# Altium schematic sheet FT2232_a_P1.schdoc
size 594 x 419 mm; Symbol: Drawing-Symbol_A4; @Project Name: FPGA_motors_V3_0; @Page Count: 1; @Update Date: 2025-11-25; @Create Date: 2025-11-25; @Schematic Name: FT2232_a; @Page No: 1; @Page Name: P1; Company: EasyEDA.com; Version: V1.0; Page Size: A4; @Create Time: 20:24:01; @Update Time: 21:28:17; Border: 1; Width: 2338; Height: 1652; Region Start: 1; X Region Count: 6; Y Region Count: 4; Blade Width: 10; Title Block Position: 3; Device: Drawing-Symbol_A4
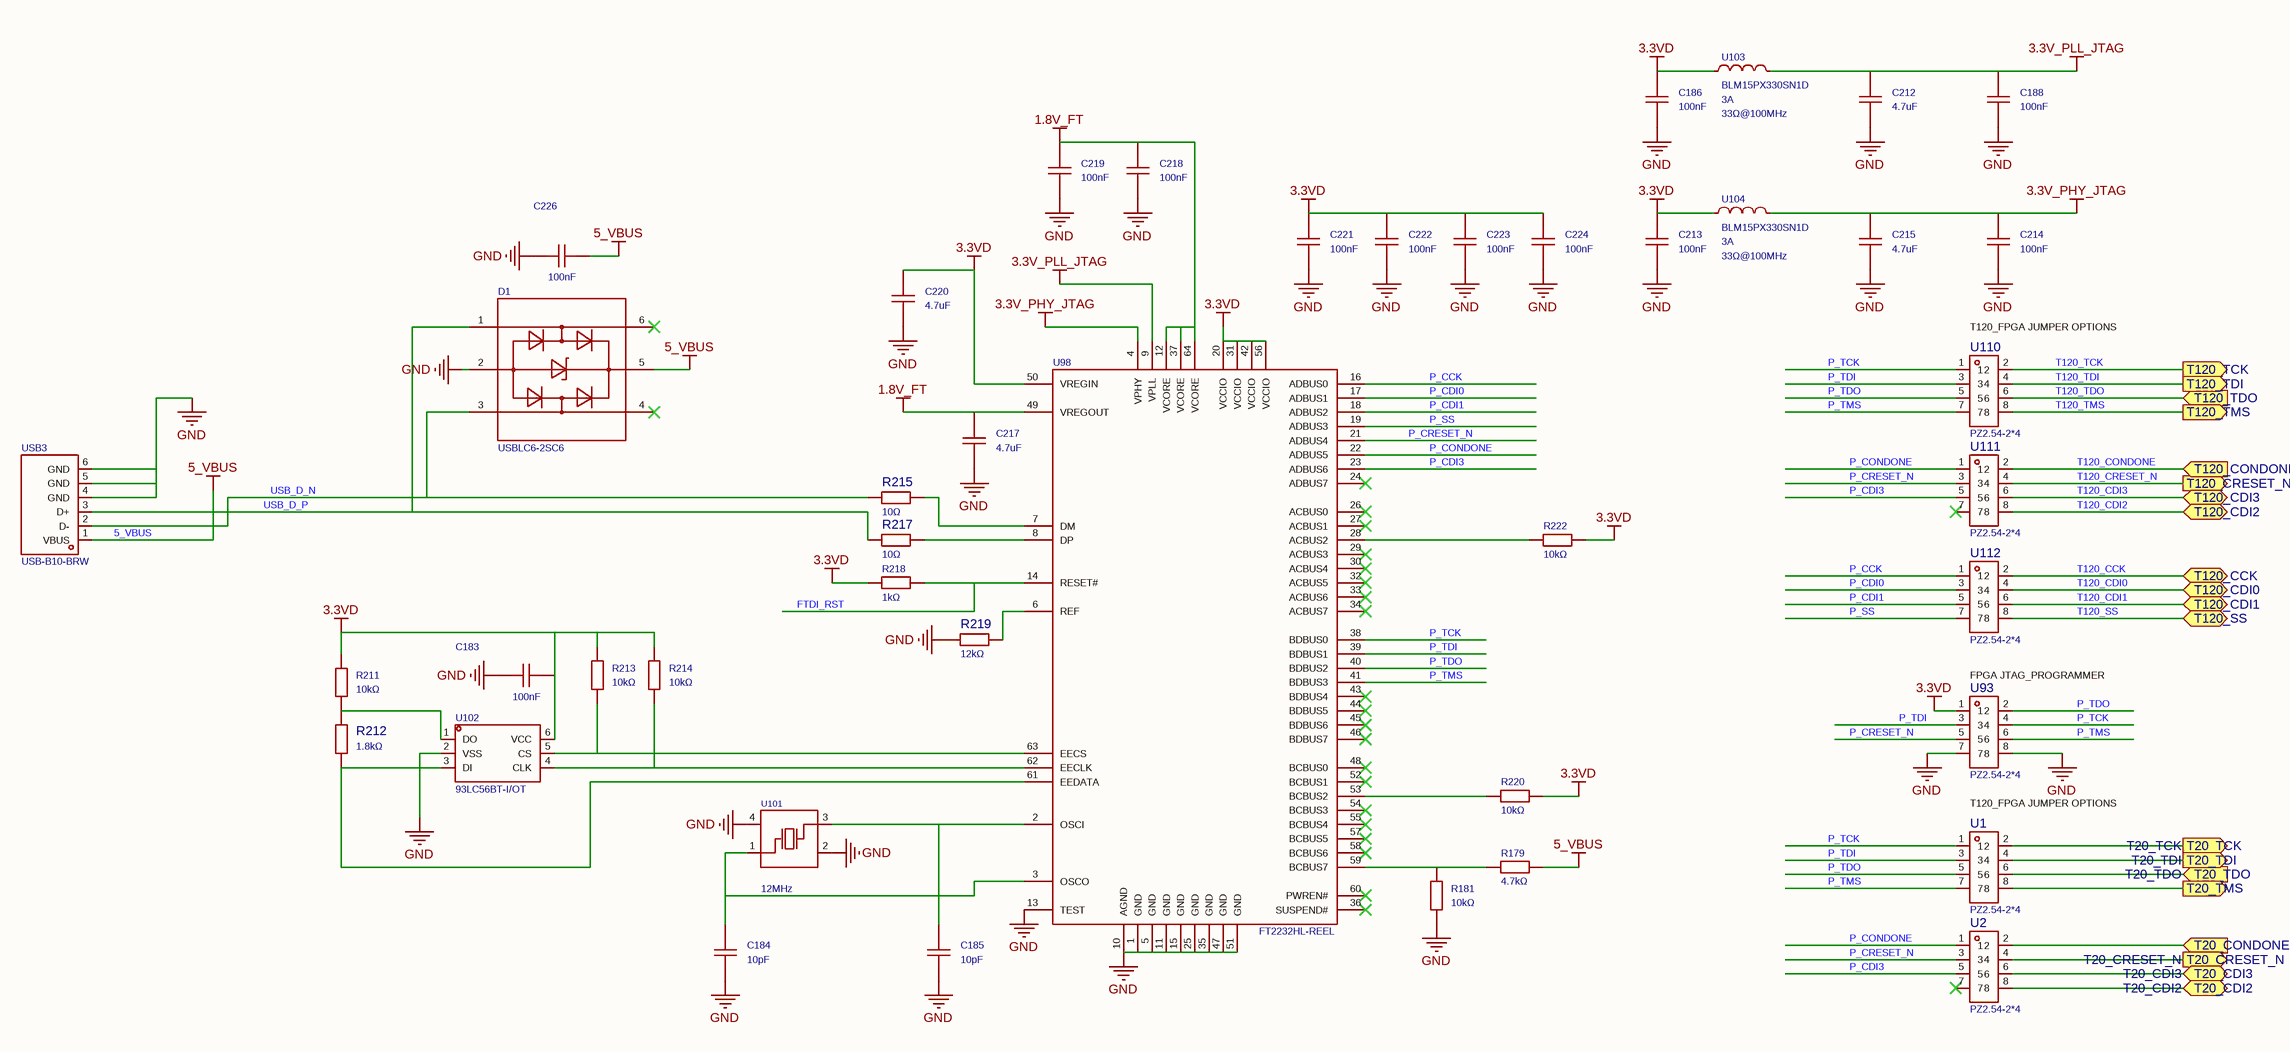
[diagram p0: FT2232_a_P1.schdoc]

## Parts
C183  100nF  [C0402]
C184  10pF  [C0402]
C185  10pF  [C0402]
C186  100nF  [C0201]
C188  100nF  [C0201]
C212  value 4.7uF  [C0402]  (hidden comment: CL05A475MP5NRNC)
C213  100nF  [C0201]
C214  100nF  [C0201]
C215  value 4.7uF  [C0402]  (hidden comment: CL05A475MP5NRNC)
C217  value 4.7uF  [C0402]  (hidden comment: CL05A475MP5NRNC)
C218  100nF  [C0201]
C219  100nF  [C0201]
C220  value 4.7uF  [C0402]  (hidden comment: CL05A475MP5NRNC)
C221  100nF  [C0201]
C222  100nF  [C0201]
C223  100nF  [C0201]
C224  100nF  [C0201]
C226  100nF  [C0402]
D1  USBLC6-2SC6  [SOT-23-6_L2.9-W1.6-P0.95-LS2.8-BL]
R179  4.7kΩ  [R0402]
R181  10kΩ  [R0402]
R211  10kΩ  [R0402]
R212  1.8kΩ  [R0402]
R213  10kΩ  [R0402]
R214  10kΩ  [R0402]
R215  10Ω  [R0402]
R217  10Ω  [R0402]
R218  1kΩ  [R0402]
R219  12kΩ  [R0402]
R220  10kΩ  [R0402]
R222  10kΩ  [R0402]
U1  PZ2.54-2*4  [HDR-TH_8P-P2.54-V-M-R2-C4-S2.54]
U2  PZ2.54-2*4  [HDR-TH_8P-P2.54-V-M-R2-C4-S2.54]
U93  PZ2.54-2*4  [HDR-TH_8P-P2.54-V-M-R2-C4-S2.54]
U98  FT2232HL-REEL  [LQFP-64_L10.0-W10.0-P0.50-LS12.0-TL]
U101  12MHz  [CRYSTAL-SMD_4P-L3.2-W2.5-BL]
U102  93LC56BT-I/OT  [SOT-23-6_L2.9-W1.6-P0.95-LS2.8-BR]
U103  BLM15PX330SN1D  Impedance @ Frequency: 33Ω@100MHz  Current Rating: 3A  [L0402]
U104  BLM15PX330SN1D  Impedance @ Frequency: 33Ω@100MHz  Current Rating: 3A  [L0402]
U110  PZ2.54-2*4  [HDR-TH_8P-P2.54-V-M-R2-C4-S2.54]
U111  PZ2.54-2*4  [HDR-TH_8P-P2.54-V-M-R2-C4-S2.54]
U112  PZ2.54-2*4  [HDR-TH_8P-P2.54-V-M-R2-C4-S2.54]
USB3  USB-B10-BRW  [USB-B-TH_USB-B10-BRW]

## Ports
T20_CDI2 (bidir), T20_CDI3 (bidir), T20_CONDONE (in), T20_CRESET_N (out), T20_TCK (out), T20_TDI (out), T20_TDO (in), T20_TMS (out), T120_CCK (bidir), T120_CDI0 (bidir), T120_CDI1 (bidir), T120_CDI2 (bidir), T120_CDI3 (bidir), T120_CONDONE (in), T120_CRESET_N (out), T120_SS (bidir), T120_TCK (out), T120_TDI (out), T120_TDO (in), T120_TMS (out)

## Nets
1.8V_FT: C217.2 C218.1 C219.1 U98.12(VCORE) U98.37(VCORE) U98.49(VREGOUT) U98.64(VCORE)
3.3V_PHY_JTAG: C214.1 C215.2 U98.4(VPHY) U104.2
3.3V_PLL_JTAG: C188.1 C212.2 U98.9(VPLL) U103.2
3.3VD: C183.2 C186.1 C213.1 C220.2 C221.1 C222.1 C223.1 C224.1 R211.2 R213.2 R214.2 R218.1 R220.1 R222.1 U93.1 U98.20(VCCIO) U98.31(VCCIO) U98.42(VCCIO) U98.50(VREGIN) U98.56(VCCIO) U102.6(VCC) U103.1 U104.1
5_VBUS: C226.2 D1.5 R179.2 USB3.1(VBUS)
GND: C183.1 C184.1 C185.1 C186.2 C188.2 C212.1 C213.2 C214.2 C215.1 C217.1 C218.2 C219.2 C220.1 C221.2 C222.2 C223.2 C224.2 C226.1 D1.2 R181.1 R219.1 U93.7 U93.8 U98.1(GND) U98.5(GND) U98.10(AGND) U98.11(GND) U98.13(TEST) U98.15(GND) U98.25(GND) U98.35(GND) U98.47(GND) U98.51(GND) U101.2(Gnd) U101.4(Gnd) U102.2(VSS) USB3.4(GND) USB3.5(GND) USB3.6(GND)
FTDI_RST: R218.2 U98.14(RESET#)
P_CCK: U98.16(ADBUS0) U112.1
P_CDI0: U98.17(ADBUS1) U112.3
P_CDI1: U98.18(ADBUS2) U112.5
P_CDI3: U2.5 U98.23(ADBUS6) U111.5
P_CONDONE: U2.1 U98.22(ADBUS5) U111.1
P_CRESET_N: U2.3 U93.5 U98.21(ADBUS4) U111.3
P_SS: U98.19(ADBUS3) U112.7
P_TCK: U1.1 U93.4 U98.38(BDBUS0) U110.1
P_TDI: U1.3 U93.3 U98.39(BDBUS1) U110.3
P_TDO: U1.5 U93.2 U98.40(BDBUS2) U110.5
P_TMS: U1.7 U93.6 U98.41(BDBUS3) U110.7
T20_CDI2: U2.8 ; port T20_CDI2
T20_CDI3: U2.6 ; port T20_CDI3
T20_CONDONE: U2.2 ; port T20_CONDONE
T20_CRESET_N: U2.4 ; port T20_CRESET_N
T20_TCK: U1.2 ; port T20_TCK
T20_TDI: U1.4 ; port T20_TDI
T20_TDO: U1.6 ; port T20_TDO
T20_TMS: U1.8 ; port T20_TMS
T120_CCK: U112.2 ; port T120_CCK
T120_CDI0: U112.4 ; port T120_CDI0
T120_CDI1: U112.6 ; port T120_CDI1
T120_CDI2: U111.8 ; port T120_CDI2
T120_CDI3: U111.6 ; port T120_CDI3
T120_CONDONE: U111.2 ; port T120_CONDONE
T120_CRESET_N: U111.4 ; port T120_CRESET_N
T120_SS: U112.8 ; port T120_SS
T120_TCK: U110.2 ; port T120_TCK
T120_TDI: U110.4 ; port T120_TDI
T120_TDO: U110.6 ; port T120_TDO
T120_TMS: U110.8 ; port T120_TMS
USB_D_N: D1.3 R215.1 USB3.2(D-)
USB_D_P: D1.1 R217.1 USB3.3(D+)
NetC184_2: C184.2 U98.3(OSCO) U101.1(In/Out)
NetC185_2: C185.2 U98.2(OSCI) U101.3(Out/In)
NetR179_1: R179.1 R181.2 U98.59(BCBUS7)
NetR211_1: R211.1 R212.2 U102.1(DO)
NetR212_1: R212.1 U98.61(EEDATA) U102.3(DI)
NetR213_1: R213.1 U98.63(EECS) U102.5(CS)
NetR214_1: R214.1 U98.62(EECLK) U102.4(CLK)
NetR215_2: R215.2 U98.7(DM)
NetR217_2: R217.2 U98.8(DP)
NetR219_2: R219.2 U98.6(REF)
NetR220_2: R220.2 U98.53(BCBUS2)
NetR222_2: R222.2 U98.28(ACBUS2)

Not connected (* = marked no-connect by the designer): D1 4* 6*; U2 7*; U98 24(ADBUS7)* 26(ACBUS0)* 27(ACBUS1)* 29(ACBUS3)* 30(ACBUS4)* 32(ACBUS5)* 33(ACBUS6)* 34(ACBUS7)* 36(SUSPEND#)* 43(BDBUS4)* 44(BDBUS5)* 45(BDBUS6)* 46(BDBUS7)* 48(BCBUS0)* 52(BCBUS1)* 54(BCBUS3)* 55(BCBUS4)* 57(BCBUS5)* 58(BCBUS6)* 60(PWREN#)*; U111 7*

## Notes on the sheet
- (near U110) T120_FPGA JUMPER OPTIONS
- (near U93) FPGA JTAG_PROGRAMMER
- T120_FPGA JUMPER OPTIONS

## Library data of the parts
C183 = CL05B104KB54PNC: Capacitance: Tolerance:±10% Tolerance:±10% Voltage Rated: Temperature Coefficient:; Manufacturer: SAMSUNG(三星); Add into BOM: no; Check: true; ConvertToPcb: yes; ModelId: b7d13df3e9464d7a99d0651d1a5b4d57; ModelName: C0402_L1.0-W0.5-H0.5; ModelTransform: 39.37,19.685,0,0,0,0,0,0,0; Tolerance: ±10%
C184 C185 = CL05C100JB5NNNC: Capacitance:10pF Tolerance:±5% Tolerance:±5% Voltage Rating:50V Temperature Coefficient:C0G; Manufacturer: SAMSUNG(三星); AddInBom: yes; ModelId: b7d13df3e9464d7a99d0651d1a5b4d57; ModelName: C0402_L1.0-W0.5-H0.5; ModelTransform: 39.37,19.685,0,0,0,0,0,0,0; Tolerance: ±5%; Voltage Rating: 50V; Temperature Coefficient: C0G
C186 C188 C213 C214 C218 C219 C221-C224 = CL03A104KP3NNNC: Capacitance:100nF Tolerance:±10% Tolerance:±10% Voltage Rating:10V Temperature Coefficient:X5R; Manufacturer: SAMSUNG(三星); Add into BOM: yes; 3D Model: c3e75c3d90204c70b153866ab54c789f; 3D Model Transform: 23.622,11.811,0,0,0,0,0,0,0; Tolerance: ±10%; Temperature Coefficient: X5R; Voltage Rating: 10V; ModelName: C0201_L0.6-W0.3-H0.3
C212 C215 C217 C220 = CL05A475MP5NRNC: Capacitance:4.7uF Tolerance:±20% Tolerance:±20% Voltage Rating:10V Temperature Coefficient:X5R; Manufacturer: SAMSUNG(三星); Temperature Coefficient: X5R; Voltage Rating: 10V; AddInBom: yes; ModelId: b7d13df3e9464d7a99d0651d1a5b4d57; ModelName: C0402_L1.0-W0.5-H0.5; ModelTransform: 39.37,19.685,0,0,0,0,0,0,0; Tolerance: ±20%
C226 = CL05B104KB54PNC: Capacitance: Tolerance:±10% Tolerance:±10% Voltage Rated: Temperature Coefficient:; Manufacturer: SAMSUNG(三星); Add into BOM: yes; Check: true; ModelId: b7d13df3e9464d7a99d0651d1a5b4d57; ModelName: C0402_L1.0-W0.5-H0.5; ModelTransform: 39.37,19.685,0,0,0,0,0,0,0; Tolerance: ±10%
D1 = USBLC6-2SC6_C7519: Polarity:Unidirectional Reverse Stand-Off Voltage (Vrwm):5.25V Clamping Voltage:17V Peak Pulse Current (Ipp):5A Voltage - Breakdown:6V Reverse Leakage Current (Ir):150nA Number of Channels:2 Operating Temperature:-40℃~+125℃ Operating Temperature:-40℃~+125; Manufacturer: ST(意法半导体); AddInBom: yes; ModelId: 1370be37a17e44418ae52e2b4cc1f5e5; ModelName: SOT-23-6_L2.9-W1.6-H1.5-LS2.8-P0.95; ModelTransform: 110.236,113.364,0,90,0,0,0.0005,0.0005,0; Reverse Stand-Off Voltage (Vrwm): 5.25V; Clamping Voltage: 17V; Peak Pulse Current (Ipp): 5A; Voltage - Breakdown: 6V; Reverse Leakage Current (Ir): 150nA; Number of Channels: 2; level of protection: IEC 61000-4-2; Type: ESD; Junction Capacitance: 3.5pF
R179 = 0402WGF4701TCE: Type:Thick Film Resistors Resistance:4.7kΩ Tolerance:±1% Tolerance:±1% Power(Watts): Overload Voltage (Max): Temperature Coefficient:±100ppm/℃ Temperature Coefficient:±100ppm/℃ Operating Temperature Range:-55℃~+155℃ Operating Temperature Range:-55℃~+155℃; Manufacturer: UNI-ROYAL(厚声); Symbol: RT0402BRD074K7L; AddInBom: yes; ModelId: efdecb7dae4442949d28eecaf748420f0819f05c4eef4c71ace90d822a990e87; ModelName: R0402_L1.0-W0.5-H0.4; ModelTransform: 39.37,19.685,0,0,0,0,0,0,0; Tolerance: ±1%; Power(Watts): 62.5mW; Voltage-Supply(Max): 50V
R181 R211 R213 R214 R220 R222 = 0402WGF1002TCE: Type:Thick Film Resistors Resistance:10kΩ Tolerance:±1% Tolerance:±1% Power(Watts): Overload Voltage (Max): Temperature Coefficient:±100ppm/℃ Temperature Coefficient:±100ppm/℃ Operating Temperature Range:-55℃~+155℃ Operating Temperature Range:-55℃~+155℃; Manufacturer: UNI-ROYAL(厚声); AddInBom: yes; ModelId: efdecb7dae4442949d28eecaf748420f; ModelName: R0402_L1.0-W0.5-H0.4; ModelTransform: 39.37,19.685,0,0,0,0,0,0,0; Tolerance: ±1%
R212 = 0402WGF1801TCE: Type:Thick Film Resistor Resistance:1.8kΩ Tolerance:±1% Tolerance:±1% Power(Watts):62.5mW Voltage-Supply(Max):50V Temperature Coefficient:±100ppm/℃ Temperature Coefficient:±100ppm/℃ Operating Temperature:-55℃~+155℃ Operating Temperature:-55℃~+155℃; Manufacturer: UNI-ROYAL(厚声); AddInBom: yes; ModelId: efdecb7dae4442949d28eecaf748420f0819f05c4eef4c71ace90d822a990e87; ModelName: R0402_L1.0-W0.5-H0.4; ModelTransform: 39.37,19.685,0,0,0,0,0,0,0; Tolerance: ±1%; Power(Watts): 62.5mW; Voltage-Supply(Max): 50V
R215 R217 = 0402WGF100JTCE: Type:Thick Film Resistor Resistance:10Ω Tolerance:±1% Tolerance:±1% Power(Watts):62.5mW Voltage-Supply(Max):50V Temperature Coefficient:±200ppm/℃ Temperature Coefficient:±200ppm/℃ Operating Temperature:-55℃~+155℃ Operating Temperature:-55℃~+155℃; Manufacturer: UNI-ROYAL(厚声); AddInBom: yes; ModelId: efdecb7dae4442949d28eecaf748420f; ModelName: R0402_L1.0-W0.5-H0.4; ModelTransform: 39.37,19.685,0,0,0,0,0,0,0; Tolerance: ±1%; Power(Watts): 62.5mW; Voltage-Supply(Max): 50V
R218 = 0402WGF1001TCE: Type:Thick Film Resistor Resistance:1kΩ Tolerance:±1% Tolerance:±1% Power(Watts):62.5mW Voltage-Supply(Max):50V Temperature Coefficient:±100ppm/℃ Temperature Coefficient:±100ppm/℃ Operating Temperature:-55℃~+155℃ Operating Temperature:-55℃~+155℃; Manufacturer: UNI-ROYAL(厚声); AddInBom: yes; ModelId: efdecb7dae4442949d28eecaf748420f0819f05c4eef4c71ace90d822a990e87; ModelName: R0402_L1.0-W0.5-H0.4; ModelTransform: 39.37,19.685,0,0,0,0,0,0,0; Tolerance: ±1%; Power(Watts): 62.5mW; Voltage-Supply(Max): 50V
R219 = 0402WGJ0123TCE: Type:Thick Film Resistor Resistance:12kΩ Tolerance:±5% Tolerance:±5% Power(Watts):62.5mW Voltage-Supply(Max):50V Temperature Coefficient:±100ppm/℃ Temperature Coefficient:±100ppm/℃ Operating Temperature:-55℃~+155℃ Operating Temperature:-55℃~+155℃; Manufacturer: UNI-ROYAL(厚声); AddInBom: yes; ModelId: efdecb7dae4442949d28eecaf748420f; ModelName: R0402_L1.0-W0.5-H0.4; ModelTransform: 39.37,19.685,0,0,0,0,0,0,0; Tolerance: ±5%; Power(Watts): 62.5mW; Voltage-Supply(Max): 50V
U1 U2 = PZ2.54-2*4: Pin Structure:2x4P Pitch:2.54mm Number of Rows:双排 Number of Pins:8P; Manufacturer: ZHOURI(洲日); Check: true; 3D Model: 47b5ce995b664298ab05f1b74b77106f; 3D Model Transform: 399.999,200,0,0,0,0,0,0,-118.11; Pin Structure: 2x4P; Pitch: 2.54mm; AddInBom: yes; ModelName: HDR-TH_8P-P2.54-M-LI-2X4P
U93 U110-U112 = PZ2.54-2*4: Pin Structure:2x4P Pitch:2.54mm Number of Rows:双排 Number of Pins:8P; Manufacturer: ZHOURI(洲日); Check: true; AddInBom: yes; ModelId: 47b5ce995b664298ab05f1b74b77106f; ModelName: HDR-TH_8P-P2.54-M-LI-2X4P; ModelTransform: 399.999,200,0,0,0,0,0,0,-118.11; Pin Structure: 2x4P; Pitch: 2.54mm
U98 = FT2232HL-REEL: Applications Function:USB to UART；USB to FIFO Protocol:- Voltage - Supply:- Voltage - Supply:- Operating Temperature:-40℃~+85℃ Operating Temperature:-40℃~+85℃; Manufacturer: FTDI(飞特帝亚); AddInBom: yes; ModelId: 9827011a374c44f2b05ac1eacaf21ae0; ModelName: LQFP-64_L10.0-W10.0-H1.4-LS12.0-P0.50; ModelTransform: 472.441,472.441,0,270,0,0,0,0,0
U101 = ECS-120-10-33B-CKM-TR: Frequency:12MHz Normal temperature Frequency Tolerance:±10ppm Normal temperature Frequency Tolerance:±10ppm External load capacitor: Frequency Stability(Full temperature range):±10ppm Frequency Stability(Full temperature range):±10ppm Equivalent Series Re; Manufacturer: ECS; AddInBom: yes; ModelId: 02485e56ba8d4732a26526d2983fc729; ModelTransform: 125.984,98.425,0,0,0,0,0,0,0; Normal temperature Frequency Tolerance: ±10ppm; Equivalent Series Resistance (ESR): 100Ω
U102 = 93LC56BT-I/OT: Interface Type:SPI Memory Size:2Kbit Supply Voltage:2.5V~5.5V Supply Voltage:2.5V~5.5V Write Cycle Time (Tw):6ms Data Retention - TDR (Year):200 years Write Cycle Endurance:1,000,000 Times Operating Temperature:-40℃~+85℃ Operating Temperature:-40℃~+85℃; Manufacturer: MICROCHIP(美国微芯); Add into BOM: no; ConvertToPcb: yes; ModelId: 1370be37a17e44418ae52e2b4cc1f5e5; ModelName: SOT-23-6_L2.9-W1.6-H1.5-LS2.8-P0.95; ModelTransform: 110.73671,114.173,0,180,0,0,0.001,-0.003,0; Interface Type: SPI; Memory Size: 2Kbit; Write Cycle Time (Tw): 6ms
U103 U104 = BLM15PX330SN1D: Impedance @ Frequency:33Ω@100MHz Tolerance:±25% Tolerance:±25% DC Resistance(DCR):22mΩ Current Rating:3A Number of Circuits:1; Manufacturer: muRata(村田); AddInBom: yes; ModelId: aef00b1603224fd68a96e37121ccc916; ModelName: L0402_L1.0-W0.5-H0.5_BEAD; ModelTransform: 39.37,19.685,0,0,0,0,0,0.0005,0; Tolerance: ±25%; DC Resistance(DCR): 22mΩ; Number of Circuits: 1
USB3 = USB-B10-BRW: Connector Type:Type-B Protocol Standard:USB 2.0 Gender:Female Mounting Type:Right Angle Number of Contacts:4P Number of Ports:1 Current Rating-Power:1.5A Voltage Rating:30V Length:16.3mm Detection color:White Operating Temperature:-20℃~+70℃ Operating Temp; Manufacturer: XUNPU(讯普); 3D Model: f77a775d8adc4bed8cfc5f075ab9dbf3; 3D Model Transform: 562.447,643.7,0,0,0,0,-0.002,-181.892,-125.984; Connector Type: Type-B; Protocol Standard: USB 2.0; Gender: Female; Number of Contacts: 4P; Number of Ports: 1; Current Rating-Power: 1.5A; Voltage Rating: 30V; Detection color: White; AddInBom: yes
